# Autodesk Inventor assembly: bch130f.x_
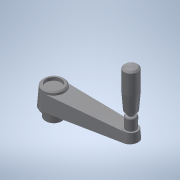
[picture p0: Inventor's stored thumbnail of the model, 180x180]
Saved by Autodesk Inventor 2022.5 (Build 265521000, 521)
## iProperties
Part Number: bch130f.x_
Material: 一般
Document SubType Name: Assembly
Designer: ImaoCorp
Sending System: SOLIDWORKS 2017-2017317
MC: AMD64
MC_MODEL: Intel64 Family 6 Model 60 Stepping 3, GenuineIntel
OS: Windows_NT
FRU: Parasolid Version 29.0, build 201,  4-17-2017
FORMAT: text
GUISE: transmit
KEY: bch130f
FILE: bch130f.x_t
DATE: Fri Mar 15 10:33:59 2019
Author: ImaoCorp
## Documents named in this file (3)
- X:\14_SW2022-Inv2022\00_全2023-1023新製品(TCC)まで\b\bch130f\BCH130F.iam
- X:\14_SW2022-Inv2022\00_全2023-1023新製品(TCC)まで\b\bch130f\bch130f_01.ipt
- X:\14_SW2022-Inv2022\00_全2023-1023新製品(TCC)まで\b\bch130f\bch130f_02.ipt
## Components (2 placed, 2 different names)
1. bch130f_01
2. bch130f_02
